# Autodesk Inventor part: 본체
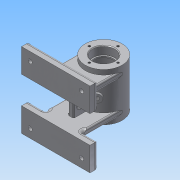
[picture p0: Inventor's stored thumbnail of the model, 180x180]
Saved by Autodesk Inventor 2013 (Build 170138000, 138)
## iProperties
Created: 2016-07
Part Number: 본체
Material: 알루미늄 6061
Document SubType Name: Modeling
Designer: Administrator
Density: 2.71 g/cm^3
Mass: 518.814 g
Surface Area: 552.241 cm^2
Volume: 191.444 cm^3
Author: Administrator
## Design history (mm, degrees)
sketch "스케치1"
  geometry: C1 r 27 at (0, 0); 1 further point
  constraints: 1 centre point, 1 coincident
  dimensions: "d0" = 54 diameter of C1
extrude "돌출1" new body sketch "스케치1" stored distance "d1" = 70; taper "d2" = 0 deg
hole "구멍1" diameter "d5" = 28; stored, may be unused: countersink angle "d9" = 90 deg, drill point angle "d11" = 0 deg; dims "d3" = 10, "d4" = 10, "d6" = 6, "d7" = 32, "d8" = 12, "d10" = 14
hole "구멍2" diameter "d14" = 28; stored, may be unused: countersink angle "d18" = 90 deg, drill point angle "d20" = 0 deg; dims "d12" = 10, "d13" = 10, "d15" = 6, "d16" = 44, "d17" = 42, "d19" = 44
hole "구멍3" diameter "d23" = 28; stored, may be unused: countersink angle "d27" = 90 deg, drill point angle "d29" = 0 deg; dims "d21" = 10, "d22" = 10, "d24" = 6, "d25" = 32, "d26" = 12, "d28" = 14
node "작업 평면1"
sketch "스케치2"
  geometry: L1 (50, 55)-(-50, 55); L2 (-50, 55)-(-50, 20); L3 (-50, 20)-(50, 20); L4 (50, 20)-(50, 55); L5 (50, -20)-(-50, -20); L6 (-50, -20)-(-50, -55); L7 (-50, -55)-(50, -55); L8 (50, -55)-(50, -20); 3 further points
  constraints: 16 end point, 4 parallel, 2 horizontal, 2 midpoint, 2 perpendicular, 2 vertical alignment
  dimensions: "d31" = 100 distance between parallel lines of L2 L4; "d33" = 100 distance between parallel lines of L6 L8; "d37" = 35 distance between parallel lines of L1 L3; "d38" = 35 distance between parallel lines of L5 L7; "d39" = 55 distance from line of L1 point (0, 0); "d40" = 55 distance from line of point (0, 0) L7
extrude "돌출2" join sketch "스케치2" distance "d41" = 12; taper "d42" = 0 deg
extrude "돌출3" join sketch "스케치2" distance "d43" = 12; taper "d44" = 0 deg
sketch "스케치3"
  geometry: L1 (50, -20)-(-50, -20) reference; L2 (-27, -28)-(27, -28); L3 (27, -28)-(27, -20); L4 (27, -20)-(-27, -20); L5 (-27, -20)-(-27, -28); 2 further points
  constraints: 8 end point, 2 midpoint, 2 parallel, 1 horizontal, 1 perpendicular
  dimensions: "d45" = 54 distance of L4.end L3.end; "d46" = 8 distance of L3.end L2.end
extrude "돌출4" join sketch "스케치3" stored distance "d47" = 12; taper "d48" = 0 deg
sketch "스케치4"
  geometry: L1 (-50, 20)-(50, 20) reference; L2 (27, 28)-(-27, 28); L3 (-27, 28)-(-27, 20); L4 (-27, 20)-(27, 20); L5 (27, 20)-(27, 28); 2 further points
  constraints: 8 end point, 2 midpoint, 2 parallel, 1 horizontal, 1 perpendicular
  dimensions: "d49" = 54 distance of L4.end L3.end; "d50" = 8 distance of L3.end L2.end
extrude "돌출5" join sketch "스케치4" stored distance "d51" = 12; taper "d52" = 0 deg
node "작업 평면3"
  node "작업 평면2"
sketch "스케치5"
  geometry: L1 (-4, 20)-(4, 20); L2 (4, 20)-(4, -20); L3 (4, -20)-(-4, -20); L4 (-4, -20)-(-4, 20); 4 further points
  constraints: 8 end point, 3 midpoint, 2 horizontal alignment, 2 parallel, 1 horizontal, 1 perpendicular, 1 vertical alignment
  dimensions: "d55" = 8 distance of L1.start L1.end; "d57" = 40 distance between parallel lines of L3 L1
extrude "돌출6" join sketch "스케치5" stored distance "d58" = 8; taper "d59" = 0 deg
sketch "스케치6"
  geometry: L1 (-3, 63.492)-(-15, 63.492) reference; L2 (-15, 63.492)-(-15, 74.702) reference; L3 (-15, 74.702)-(55, 74.702) reference; L4 (55, 74.702)-(55, 63.492) reference; L5 (55, 63.492)-(43, 63.492) reference; L6 (43, 63.492)-(43, 61.416) reference; L7 (43, 61.416)-(41, 61.416) reference; L8 (41, 61.416)-(41, 69.633) reference; L9 (41, 69.633)-(-1, 69.633) reference; L10 (-1, 69.633)-(-1, 61.416) reference; L11 (-1, 61.416)-(-3, 61.416) reference; L12 (-3, 61.416)-(-3, 63.492) reference; L13 (-35, -22)-(-35, -10) reference; L14 (-35, -10)-(-8, -10) reference; L15 (-8, -10)-(-8, 21.298) reference; L16 (-8, 21.298)-(-15, 21.298) reference; L17 (-15, 21.298)-(-15, 32.508) reference; L18 (-15, 32.508)-(-3, 32.508) reference; L19 (-3, 32.508)-(-3, 34.584) reference; L20 (-3, 34.584)-(-1, 34.584) reference; L21 (-1, 34.584)-(-1, 26.367) reference; L22 (-1, 26.367)-(41, 26.367) reference; L23 (41, 26.367)-(41, 34.584) reference; L24 (41, 34.584)-(43, 34.584) reference; L25 (43, 34.584)-(43, 32.508) reference; L26 (43, 32.508)-(55, 32.508) reference; L27 (55, 32.508)-(55, 21.298) reference; L28 (55, 21.298)-(48, 21.298) reference; L29 (48, 21.298)-(48, -10) reference; L30 (48, -10)-(75, -10) reference; L31 (75, -10)-(75, -22) reference; L32 (75, -22)-(40, -22) reference; L33 (40, -22)-(40, 0) reference; L34 (40, 0)-(0, 0) reference; L35 (0, 21.298)-(0, 0) reference; L36 (40, 21.298)-(0, 21.298) reference; L37 (40, 0)-(40, 21.298) reference; L38 (0, -22)-(-35, -22) reference; L39 (0, 0)-(0, -22) reference; L40 (12, 6.5)-(28, 6.5); L41 (28, 13.5)-(12, 13.5); L42 (20, 13.5)-(20, 6.5); L43 (-15, 75)-(-15, 21) reference; A1 r 3.5 centre (12, 10) between (12, 13.5) and (12, 6.5); A2 r 3.5 centre (28, 10) between (28, 6.5) and (28, 13.5); 1 further point
  constraints: 6 end point, 4 point on circle, 3 tangent, 2 centre point, 2 midpoint, 1 horizontal alignment
  dimensions: "d60" = 7 diameter of A1; "d61" = 7 diameter of A2; "d62" = 32 distance from line of L38 A1.centre; "d63" = 23 dimension on A2 A1; "d64" = 35 distance between parallel lines of L42 L43
extrude "돌출7" cut sketch "스케치6" stored distance "d65" = 8; taper "d66" = 0 deg
node "작업 평면5"
  node "작업 평면4"
sketch "스케치7"
  geometry: L1 (-27, -35)-(27, -35) reference; C1 r 5 at (0, -13); 1 further point
  constraints: 1 centre point, 1 vertical alignment
  dimensions: "d68" = 10 diameter of C1; "d70" = 22 distance from line of L1 C1.centre
extrude "돌출8" join sketch "스케치7" stored distance "d71" = 8; taper "d72" = 0 deg
sketch "스케치8"
  geometry: C1 r 5 at (0, 0) reference; 2 further points
  constraints: 1 coincident
hole "구멍4" sketch "스케치8" at (0, 0) diameter "d73" = 5.188; stored, may be unused: countersink angle "d77" = 90 deg, drill point angle "d79" = 0 deg; dims "d74" = 6, "d75" = 32, "d76" = 12, "d78" = 14
node "작업 평면6"
sketch "스케치9"
  geometry: L1 (0, 0)-(30, 0); L2 (0, 0)-(15.898, -25.441); L3 (0, 0)-(30, 0); L4 (4, -48)-(-4, -48) reference; L5 (-4, -48)-(-4, -41.5) reference; L6 (-4, -41.5)-(4, -41.5) reference; L7 (4, -41.5)-(4, -48) reference; L8 (4, -26.702)-(4, -34.5) reference; L9 (4, -34.5)-(-4, -34.5) reference; L10 (-4, -34.5)-(-4, -26.702) reference; C1 r 22 at (0, 0) reference; A1 r 27 centre (0, 0) between (4, -26.702) and (-4, -26.702) reference
  constraints: 6 end point, 2 horizontal, 1 equal length
  dimensions: "d83" = 30 distance of L1.start L2.end; "d84" = 58 deg angle of L2 L3
  node "절단 모서리 투영2"
node "작업 평면7"
sketch "스케치12"
  geometry: C1 r 16 at (0, 0) reference; 1 further point
  constraints: 1 vertical alignment
  dimensions: "d95" = 21 distance of C1.centre point (0, 21)
hole "구멍6" sketch "스케치12" at (0, 21) diameter "d96" = 3.242; stored, may be unused: countersink angle "d100" = 90 deg, drill point angle "d102" = 118 deg; dims "d97" = 8, "d98" = 32, "d99" = 12, "d101" = 10
sketch "스케치13"
  geometry: C1 r 16 at (0, 0) reference; 1 further point
  constraints: 1 vertical alignment
  dimensions: "d106" = 21 distance of C1.centre point (0, 21)
hole "구멍7" sketch "스케치13" at (0, 21) diameter "d107" = 3.242; stored, may be unused: countersink angle "d111" = 90 deg, drill point angle "d113" = 118 deg; dims "d108" = 8, "d109" = 32, "d110" = 12, "d112" = 10
sketch "스케치14"
  geometry: L1 (27, 20)-(50, 20) reference; L2 (50, 20)-(50, 55) reference; L3 (-50, 55)-(-50, 20) reference; L4 (-50, 20)-(-27, 20) reference; L5 (50, -55)-(50, -20) reference; L6 (-50, -20)-(-50, -55) reference; L7 (-27, -20)-(-50, -20) reference; L8 (50, -20)-(27, -20) reference; 5 further points
  dimensions: "d117" = 12.5 distance from line of L3 point (-37.5, 42.5); "d118" = 12.5 distance from line of L2 point (37.5, 42.5); "d119" = 12.5 distance from line of L5 point (37.5, -42.5); "d120" = 12.5 distance from line of L6 point (-37.5, -42.5); "d122" = 22.5 distance from line of L4 point (-37.5, 42.5); "d123" = 22.5 distance from line of L1 point (37.5, 42.5); "d124" = 22.5 distance from line of L7 point (-37.5, -42.5); "d125" = 22.5 distance from line of L8 point (37.5, -42.5)
hole "구멍8" sketch "스케치14" at (-37.5, 42.5), (37.5, 42.5), (-37.5, -42.5), (37.5, -42.5) diameter "d126" = 6; stored, may be unused: countersink angle "d130" = 90 deg, drill point angle "d132" = 0 deg; dims "d127" = 8, "d128" = 10, "d129" = 4, "d131" = 10
fillet "모깎기1" dims "d133" = 3
fillet "모깎기2" dims "d134" = 0.3
fillet "모깎기3" dims "d135" = 0.3
chamfer "모따기1" distance "d136" = 1; stored, may be unused: second distance "d137" = 2, angle "d138" = 110 deg
fillet "모깎기4" dims "d139" = 2
fillet "모깎기5" dims "d140" = 2
fillet "모깎기6" dims "d141" = 2
fillet "모깎기7" dims "d142" = 5
node "작업 평면8"
fillet "모깎기8" dims "d146" = 2
fillet "모깎기9" dims "d147" = 2
sketch "스케치16"
  geometry: L1 (-2, -41.5)-(2, -41.5) reference; L2 (4, -43.5)-(4, -46) reference; L3 (2, -48)-(-2, -48) reference; L4 (-4, -46)-(-4, -43.5) reference; L5 (4, -28.373)-(4, -32.5) reference; L6 (2, -34.5)-(-2, -34.5) reference; L7 (-4, -32.5)-(-4, -28.373) reference; L8 (0, 0)-(15.898, -25.441); L9 (0, 0)-(30, 0); C1 r 22 at (0, 0) reference; A1 r 2 centre (-2, -43.5) between (-2, -41.5) and (-4, -43.5) reference; A2 r 2 centre (2, -43.5) between (4, -43.5) and (2, -41.5) reference; A3 r 2 centre (2, -46) between (2, -48) and (4, -46) reference; A4 r 2 centre (-2, -46) between (-4, -46) and (-2, -48) reference; A5 r 27 centre (0, 0) between (5.586, -26.416) and (-5.586, -26.416) reference; A6 r 2 centre (6, -28.373) between (5.586, -26.416) and (4, -28.373) reference; A7 r 2 centre (2, -32.5) between (2, -34.5) and (4, -32.5) reference; A8 r 2 centre (-2, -32.5) between (-4, -32.5) and (-2, -34.5) reference; A9 r 2 centre (-6, -28.373) between (-4, -28.373) and (-5.586, -26.416) reference; 1 further point
  constraints: 4 end point, 1 equal length, 1 horizontal
  dimensions: "d148" = 30 distance of L8.start L8.end; "d149" = 58 deg angle of L8 L9
  node "절단 모서리 투영4"
node "작업 평면9"
sketch "스케치17"
  geometry: C1 r 6 at (0, 0); 1 further point
  constraints: 1 centre point, 1 coincident
  dimensions: "d150" = 12 diameter of C1
extrude "돌출10" join sketch "스케치17" stored distance "d151" = 8; taper "d152" = 0 deg
sketch "스케치18"
  geometry: C1 r 6 at (0, 0) reference; 1 further point
  constraints: 1 coincident
hole "구멍9" sketch "스케치18" at (0, 0) diameter "d153" = 5.188; stored, may be unused: countersink angle "d157" = 90 deg, drill point angle "d159" = 118 deg; dims "d154" = 8, "d155" = 10, "d156" = 4, "d158" = 10
node "작업 평면10"
sketch "스케치19"
  geometry: L1 (62.708, -20)-(70, -20) reference; L2 (70, -20)-(70, -55) reference; L3 (70, -55)-(63, -55) reference; L4 (58, -50)-(58, -29.464) reference; L5 (56, -26)-(0, -26) reference; L6 (0, -26)-(0, -22) reference; L7 (0, -22)-(0, 22) reference; L8 (53.764, 22)-(0, 22) reference; L9 (56, 25)-(56, 26) reference; L10 (58, 29.464)-(58, 50) reference; L11 (63, 55)-(70, 55) reference; L12 (70, 55)-(70, 20) reference; L13 (70, 20)-(62.708, 20) reference; L14 (53.764, -22)-(0, -22) reference; L15 (56, -26)-(56, -25) reference; L16 (0, -35)-(0, -26) reference; L17 (0, 22)-(0, 26) reference; L18 (56, 26)-(0, 26) reference; L19 (0, 26)-(0, 35) reference; A1 r 5 centre (63, -50) between (58, -50) and (63, -55) reference; A2 r 5 centre (63, 50) between (63, 55) and (58, 50) reference; 3 further points
  constraints: 1 coincident, 1 midpoint, 7 other
feature "엠보싱2" sketch "스케치19" dims "d31" = 100, "d37" = 35, "d39" = 55, "d160" = 0.5, "d161" = 0
node "솔리드1"
pattern_circular "원형 패턴1" dims angle "d104" = 360 deg
pattern_circular "원형 패턴2" dims angle "d115" = 360 deg
node "절단 모서리 투영1"
node "절단 모서리 투영5"
other parameters: "d53" = -21, "d67" = 3, "d80" = -35
